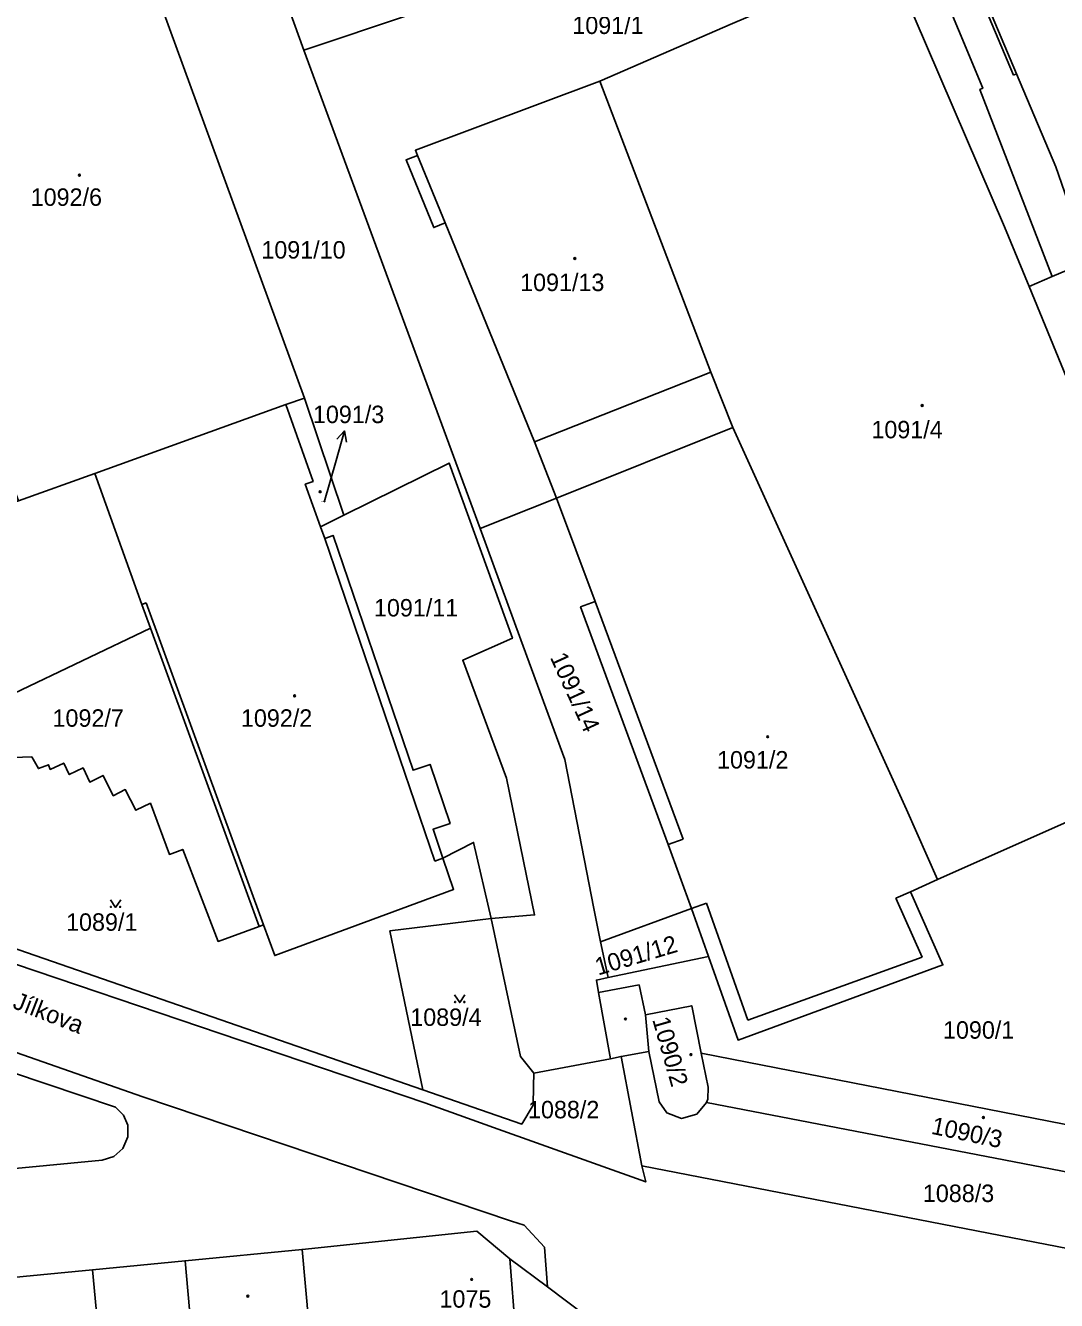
# Model space of a CAD drawing. Extents: x -596233 to -595156, y -1161235 to -1159375.
# Drawn here: x -596146 to -596045.4, y -1160887.6 to -1160763.3 of the extents above; entities that cross this region are included whole.
import ezdxf

# ---------------------------------------------------------------- set-up
doc = ezdxf.new("R2010")
doc.units = 0
for name, color, linetype in [('KN_CAR_KR', 7, 'Continuous'), ('KN_KULTURY', 7, 'Continuous'), ('KN_PARC_CIS_POM', 7, 'Continuous'), ('KN_PARC_CIS_POZ', 7, 'Continuous'), ('KN_PARC_CIS_STAV', 7, 'Continuous'), ('KN_PARC_PLOCHA', 7, 'Continuous'), ('KN_ULICE', 7, 'Continuous'), ('PARC_C_SIPKA', 7, 'Continuous'), ('parcely_l', 7, 'Continuous')]:
    doc.layers.add(name, color=color, linetype=linetype)

msp = doc.modelspace()

# ---------------------------------------------------------------- linework, layer by layer
at = {"layer": 'KN_CAR_KR'}
for points in [[(-596072.15, -1160714.71), (-596049.62, -1160768.1)], [(-596049.34, -1160767.98), (-596049.62, -1160768.1)], [(-596107.74, -1160775.93), (-596105.04, -1160782.51)], [(-596096.32, -1160803.86), (-596079.15, -1160797.08)], [(-596116.78, -1160813.27), (-596106.06, -1160844.74)], [(-596134.2, -1160819.54), (-596134.62, -1160819.7)], [(-596134.2, -1160819.54), (-596122.75, -1160850.94)], [(-596090.43, -1160819.42), (-596081.84, -1160842.59)], [(-596081.84, -1160842.59), (-596083.29, -1160843.12)], [(-596105.26, -1160844.44), (-596106.06, -1160844.74)], [(-596059.69, -1160847.71), (-596061.11, -1160848.34)], [(-596058.55, -1160854.09), (-596061.11, -1160848.34)], [(-596081.02, -1160849.36), (-596079.57, -1160848.83)], [(-596079.57, -1160848.83), (-596075.54, -1160860.23)], [(-596075.54, -1160860.23), (-596058.55, -1160854.09)], [(-596085.5, -1160859.72), (-596085.19, -1160863.29)]]:
    msp.add_lwpolyline(points, dxfattribs=at)
at = {"layer": 'KN_KULTURY'}
for points in [[(-596137.6818, -1160848.4916), (-596137.1818, -1160849.2416), (-596136.6818, -1160848.4916)], [(-596104.1218, -1160857.7616), (-596103.6218, -1160858.5116), (-596103.1218, -1160857.7616)]]:
    msp.add_lwpolyline(points, dxfattribs=at)
for centre, radius in [((-596140.71, -1160777.86), 0.09), ((-596140.71, -1160777.86), 0.0398), ((-596092.41, -1160785.98), 0.09), ((-596092.41, -1160785.98), 0.0398), ((-596058.53, -1160800.32), 0.09), ((-596058.53, -1160800.32), 0.0398), ((-596117.24, -1160808.72), 0.09), ((-596117.24, -1160808.72), 0.0398), ((-596119.72, -1160828.62), 0.09), ((-596119.72, -1160828.62), 0.0398), ((-596073.6, -1160832.6), 0.09), ((-596073.6, -1160832.6), 0.0398), ((-596137.632, -1160849.1914), 0.05), ((-596136.7326, -1160849.1914), 0.05), ((-596104.072, -1160858.4614), 0.05), ((-596103.1726, -1160858.4614), 0.05), ((-596087.47, -1160860.12), 0.09), ((-596087.47, -1160860.12), 0.0398), ((-596081.08, -1160863.59), 0.09), ((-596081.08, -1160863.59), 0.0398), ((-596052.57, -1160869.72), 0.09), ((-596052.57, -1160869.72), 0.0398), ((-596102.46, -1160885.5), 0.09), ((-596102.46, -1160885.5), 0.0398), ((-596124.29, -1160887.14), 0.09), ((-596124.29, -1160887.14), 0.0398)]:
    msp.add_circle(centre, radius, dxfattribs=at)
at = {"layer": 'KN_PARC_PLOCHA'}
for points in [[(-596000.33, -1160909.55), (-596007.39, -1160887.14), (-596011.7, -1160881.28), (-596019.9, -1160853.74), (-596021.03, -1160850.45), (-596021.41, -1160848.45), (-596026.6, -1160833.01), (-596028.99, -1160825.87), (-596038.75, -1160796.73), (-596042.32, -1160786.24), (-596045.52, -1160777.05), (-596049.34, -1160767.98), (-596071.87, -1160714.59), (-596073.58, -1160710.49), (-596068.84, -1160708.45), (-596077.52, -1160688.01)], [(-596136.48, -1160716.79), (-596118.84, -1160765.69), (-596101.64, -1160812.31), (-596097.66, -1160823.15), (-596093.37, -1160834.81), (-596090.56, -1160849.36), (-596089.9, -1160852.59), (-596089.16, -1160856.08), (-596090.3, -1160856.32), (-596090.08, -1160857.55), (-596088.92, -1160863.99), (-596096.41, -1160865.4), (-596097.7, -1160863.78), (-596100.56, -1160850.33), (-596096.33, -1160849.98), (-596099.08, -1160836.65), (-596103.33, -1160825.15), (-596098.49, -1160823.01), (-596104.65, -1160805.93), (-596114.93, -1160810.99), (-596118.75, -1160799.6), (-596137.5, -1160748.21)], [(-596059.58, -1160752.69), (-596052.63, -1160769.38), (-596052.9, -1160769.5), (-596045.86, -1160787.75), (-596048.11, -1160788.71), (-596050.5, -1160782.91), (-596061.82, -1160756.58)], [(-596077.03, -1160763.09), (-596089.98, -1160768.71), (-596107.94, -1160775.43), (-596107.74, -1160775.93), (-596108.85, -1160776.38), (-596106.16, -1160782.97), (-596105.04, -1160782.51), (-596096.32, -1160803.86), (-596094.2, -1160809.34), (-596101.64, -1160812.31), (-596118.84, -1160765.69), (-596108.43, -1160762.2)], [(-596152.74, -1160834.82), (-596145.36, -1160834.57), (-596144.7, -1160835.71), (-596143.73, -1160835.33), (-596143.55, -1160835.79), (-596142.23, -1160835.17), (-596141.7, -1160836.29), (-596140.34, -1160835.65), (-596139.69, -1160837.02), (-596138.4, -1160836.37), (-596137.4, -1160838.35), (-596136.23, -1160837.76), (-596135.21, -1160839.77), (-596133.78, -1160839.09), (-596131.93, -1160844.08), (-596130.63, -1160843.58), (-596127.18, -1160852.56), (-596123.17, -1160851.1), (-596122.75, -1160850.94), (-596121.66, -1160853.93), (-596104.23, -1160847.48), (-596105.26, -1160844.44), (-596102.27, -1160842.91), (-596100.56, -1160850.33), (-596110.43, -1160851.53), (-596107.22, -1160867.02), (-596171.31, -1160844.82)], [(-596027.09, -1160873.82), (-596080.08, -1160863.44), (-596081, -1160858.83), (-596085.5, -1160859.72), (-596086.13, -1160856.79), (-596090.08, -1160857.55), (-596090.3, -1160856.32), (-596089.16, -1160856.08), (-596079.37, -1160854.02), (-596076.49, -1160862.18), (-596056.52, -1160854.84), (-596059.69, -1160847.71), (-596057.04, -1160846.53), (-596033.57, -1160836.1)], [(-596168.84, -1160847.35), (-596107.03, -1160868.29), (-596100.34, -1160870.7), (-596085.49, -1160876), (-596085.86, -1160874.42), (-596010.41, -1160889.08)], [(-596200.45, -1160893.61), (-596199.88, -1160880.8), (-596201.49, -1160880.22), (-596202.73, -1160877.09), (-596202.04, -1160860.49), (-596201.91, -1160858.83), (-596201.86, -1160856.94), (-596199.63, -1160855.05), (-596180.91, -1160853.37), (-596176.85, -1160853.65), (-596170.3, -1160855.19), (-596134.51, -1160867.71), (-596098.58, -1160879.83), (-596097.34, -1160880.21), (-596095.37, -1160882.37), (-596095.08, -1160886.24), (-596098.74, -1160883.49), (-596101.95, -1160880.79), (-596118.99, -1160882.58), (-596130.41, -1160883.69), (-596139.42, -1160884.56), (-596153.99, -1160885.97), (-596163, -1160886.84), (-596171.46, -1160887.66)], [(-596083.82, -1160894.71), (-596095.08, -1160886.24), (-596095.37, -1160882.37), (-596097.34, -1160880.21), (-596098.58, -1160879.83), (-596134.51, -1160867.71), (-596170.3, -1160855.19)], [(-596097.64, -1160897.55), (-596098.74, -1160883.49), (-596095.08, -1160886.24), (-596083.82, -1160894.71)]]:
    msp.add_lwpolyline(points, dxfattribs=at)
for points in [[(-596118.84, -1160765.69), (-596136.48, -1160716.79), (-596124.3, -1160710.76), (-596108, -1160702.81), (-596087.28, -1160692.71), (-596087.37, -1160692.59), (-596086.66, -1160692.24), (-596082.71, -1160700.79), (-596087.62, -1160703.18), (-596086.79, -1160704.91), (-596089.87, -1160706.41), (-596086.76, -1160713.86), (-596082.9, -1160712.34), (-596067.77, -1160750.79), (-596096.45, -1160762.05), (-596111.56, -1160723.59), (-596107.01, -1160721.76), (-596109.61, -1160715.2), (-596122.95, -1160721.71), (-596112.01, -1160744.47), (-596104.98, -1160760.52), (-596108.43, -1160762.2)], [(-596042.32, -1160786.24), (-596045.86, -1160787.75), (-596052.9, -1160769.5), (-596052.63, -1160769.38), (-596059.58, -1160752.69), (-596058.71, -1160752.32), (-596073.95, -1160715.48), (-596072.15, -1160714.71), (-596071.87, -1160714.59), (-596049.34, -1160767.98), (-596045.52, -1160777.05)], [(-596118.75, -1160799.6), (-596120.58, -1160800.23), (-596139.2, -1160806.93), (-596146.64, -1160809.6), (-596163.39, -1160764.31), (-596175.3, -1160768.35), (-596177.14, -1160762.95), (-596137.5, -1160748.21)], [(-596177.14, -1160762.95), (-596175.3, -1160768.35), (-596158.5, -1160813.85), (-596146.64, -1160809.6), (-596139.2, -1160806.93), (-596134.62, -1160819.7), (-596133.78, -1160822.01), (-596153.81, -1160831.58), (-596157.33, -1160820.92), (-596182.87, -1160824.1), (-596185.5, -1160814.72), (-596176.78, -1160812.84), (-596185.99, -1160770.64), (-596197.16, -1160773.1), (-596199.82, -1160763.59), (-596180.21, -1160753.92)], [(-596048.11, -1160788.71), (-596043.93, -1160798.86), (-596031.4, -1160826.94), (-596028.36, -1160833.79), (-596033.57, -1160836.1), (-596057.04, -1160846.53), (-596060.08, -1160839.68), (-596077, -1160802.47), (-596079.15, -1160797.08), (-596089.98, -1160768.71), (-596077.03, -1160763.09), (-596061.82, -1160756.58), (-596050.5, -1160782.91)], [(-596077, -1160802.47), (-596094.2, -1160809.34), (-596096.32, -1160803.86), (-596105.04, -1160782.51), (-596106.16, -1160782.97), (-596108.85, -1160776.38), (-596107.74, -1160775.93), (-596107.94, -1160775.43), (-596089.98, -1160768.71), (-596079.15, -1160797.08)], [(-596028.99, -1160825.87), (-596031.4, -1160826.94), (-596043.93, -1160798.86), (-596048.11, -1160788.71), (-596045.86, -1160787.75), (-596042.32, -1160786.24), (-596038.75, -1160796.73)], [(-596117.19, -1160812.14), (-596116.78, -1160813.27), (-596115.98, -1160812.98), (-596108.18, -1160835.87), (-596106.52, -1160835.3), (-596104.56, -1160841.06), (-596106.22, -1160841.62), (-596105.26, -1160844.44), (-596104.23, -1160847.48), (-596121.66, -1160853.93), (-596122.75, -1160850.94), (-596123.17, -1160851.1), (-596133.78, -1160822.01), (-596134.62, -1160819.7), (-596139.2, -1160806.93), (-596120.58, -1160800.23), (-596117.93, -1160807.72), (-596118.68, -1160807.99)], [(-596114.93, -1160810.99), (-596117.19, -1160812.14), (-596118.68, -1160807.99), (-596117.93, -1160807.72), (-596120.58, -1160800.23), (-596118.75, -1160799.6)], [(-596057.04, -1160846.53), (-596059.69, -1160847.71), (-596056.52, -1160854.84), (-596076.49, -1160862.18), (-596079.37, -1160854.02), (-596081.02, -1160849.36), (-596083.29, -1160843.12), (-596091.84, -1160819.95), (-596090.43, -1160819.42), (-596094.2, -1160809.34), (-596077, -1160802.47), (-596060.08, -1160839.68)], [(-596100.56, -1160850.33), (-596102.27, -1160842.91), (-596105.26, -1160844.44), (-596106.22, -1160841.62), (-596104.56, -1160841.06), (-596106.52, -1160835.3), (-596108.18, -1160835.87), (-596115.98, -1160812.98), (-596116.78, -1160813.27), (-596117.19, -1160812.14), (-596114.93, -1160810.99), (-596104.65, -1160805.93), (-596098.49, -1160823.01), (-596103.33, -1160825.15), (-596099.08, -1160836.65), (-596096.33, -1160849.98)], [(-596081.02, -1160849.36), (-596089.9, -1160852.59), (-596090.56, -1160849.36), (-596093.37, -1160834.81), (-596097.66, -1160823.15), (-596101.64, -1160812.31), (-596094.2, -1160809.34), (-596090.43, -1160819.42), (-596091.84, -1160819.95), (-596083.29, -1160843.12)], [(-596123.17, -1160851.1), (-596127.18, -1160852.56), (-596130.63, -1160843.58), (-596131.93, -1160844.08), (-596133.78, -1160839.09), (-596135.21, -1160839.77), (-596136.23, -1160837.76), (-596137.4, -1160838.35), (-596138.4, -1160836.37), (-596139.69, -1160837.02), (-596140.34, -1160835.65), (-596141.7, -1160836.29), (-596142.23, -1160835.17), (-596143.55, -1160835.79), (-596143.73, -1160835.33), (-596144.7, -1160835.71), (-596145.36, -1160834.57), (-596152.74, -1160834.82), (-596153.81, -1160831.58), (-596133.78, -1160822.01)], [(-596107.22, -1160867.02), (-596097.58, -1160870.36), (-596096.48, -1160868.53), (-596096.44, -1160866.67), (-596096.41, -1160865.4), (-596088.92, -1160863.99), (-596087.89, -1160863.76), (-596085.86, -1160874.42), (-596085.49, -1160876), (-596100.34, -1160870.7), (-596107.03, -1160868.29), (-596168.84, -1160847.35), (-596175.49, -1160845.77), (-596180.4, -1160845.39), (-596181.92, -1160845.45), (-596178.19, -1160843.57), (-596177.81, -1160843.55), (-596171.31, -1160844.82)], [(-596079.37, -1160854.02), (-596089.16, -1160856.08), (-596089.9, -1160852.59), (-596081.02, -1160849.36)], [(-596096.41, -1160865.4), (-596096.44, -1160866.67), (-596096.48, -1160868.53), (-596097.58, -1160870.36), (-596107.22, -1160867.02), (-596110.43, -1160851.53), (-596100.56, -1160850.33), (-596097.7, -1160863.78)], [(-596138.5, -1160873.88), (-596191.79, -1160878.99), (-596191.14, -1160856.53), (-596179.67, -1160855.28), (-596176.6, -1160855.55), (-596174.51, -1160856.16), (-596137.2, -1160868.71), (-596136.41, -1160869.5), (-596136, -1160870.46), (-596135.98, -1160871.59), (-596136.48, -1160872.74), (-596137.35, -1160873.52)], [(-596138.5, -1160873.88), (-596137.35, -1160873.52), (-596136.48, -1160872.74), (-596135.98, -1160871.59), (-596136, -1160870.46), (-596136.41, -1160869.5), (-596137.2, -1160868.71), (-596174.51, -1160856.16), (-596176.6, -1160855.55), (-596179.67, -1160855.28), (-596191.14, -1160856.53), (-596191.79, -1160878.99)], [(-596080.08, -1160863.44), (-596079.41, -1160866.78), (-596079.43, -1160867.93), (-596079.56, -1160868.27), (-596080.51, -1160869.4), (-596081.99, -1160869.81), (-596083.44, -1160869.28), (-596084.19, -1160868.2), (-596085.19, -1160863.29), (-596087.89, -1160863.76), (-596088.92, -1160863.99), (-596090.08, -1160857.55), (-596086.13, -1160856.79), (-596085.5, -1160859.72), (-596081, -1160858.83)], [(-596079.56, -1160868.27), (-596026.81, -1160878.44), (-596019.85, -1160879.75), (-596011.7, -1160881.28), (-596007.39, -1160887.14), (-596000.33, -1160909.55), (-596012, -1160905.25), (-596014.53, -1160904.19), (-596006.25, -1160900.53), (-596009.92, -1160899.18), (-596010.61, -1160897.55), (-596010.41, -1160889.08), (-596085.86, -1160874.42), (-596087.89, -1160863.76), (-596085.19, -1160863.29), (-596084.19, -1160868.2), (-596083.44, -1160869.28), (-596081.99, -1160869.81), (-596080.51, -1160869.4)], [(-596026.81, -1160878.44), (-596079.56, -1160868.27), (-596079.43, -1160867.93), (-596079.41, -1160866.78), (-596080.08, -1160863.44), (-596027.09, -1160873.82), (-596026.58, -1160878.07)], [(-596098.74, -1160883.49), (-596097.64, -1160897.55), (-596107.71, -1160898.29), (-596107.94, -1160898.31), (-596111.91, -1160898.65), (-596117.49, -1160899.12), (-596117.88, -1160894.84), (-596118.01, -1160893.42), (-596118.99, -1160882.58), (-596101.95, -1160880.79)], [(-596117.88, -1160894.84), (-596123.34, -1160895.34), (-596123.08, -1160898.14), (-596122.97, -1160899.12), (-596124.24, -1160900.95), (-596129.06, -1160901.42), (-596129.09, -1160898.69), (-596129.09, -1160898.46), (-596129.17, -1160897.57), (-596130.41, -1160883.69), (-596118.99, -1160882.58), (-596118.01, -1160893.42)], [(-596137.68, -1160903.28), (-596137.46, -1160905.73), (-596137.39, -1160906.48), (-596144.44, -1160906.38), (-596144.93, -1160901.29), (-596145.14, -1160899.13), (-596145.03, -1160899.12), (-596145.23, -1160897.26), (-596149.52, -1160897.65), (-596149.91, -1160901.78), (-596153.2, -1160902.09), (-596152.84, -1160897.91), (-596153.99, -1160885.97), (-596139.42, -1160884.56), (-596138.13, -1160898.4)], [(-596129.06, -1160901.42), (-596129.05, -1160902.48), (-596137.68, -1160903.28), (-596138.13, -1160898.4), (-596139.42, -1160884.56), (-596130.41, -1160883.69), (-596129.17, -1160897.57), (-596129.09, -1160898.46), (-596129.09, -1160898.69)]]:
    msp.add_lwpolyline(points, close=True, dxfattribs=at)
at = {"layer": 'PARC_C_SIPKA'}
for points in [[(-596116.83, -1160809.73), (-596115.68, -1160805.67), (-596114.8619, -1160802.7837)], [(-596115.6156, -1160803.6095), (-596114.8619, -1160802.7837), (-596114.6535, -1160803.8822)]]:
    msp.add_lwpolyline(points, dxfattribs=at)
at = {"layer": 'parcely_l'}
for points in [[(-596086.66, -1160692.24), (-596082.71, -1160700.79), (-596087.62, -1160703.18), (-596086.79, -1160704.91), (-596089.87, -1160706.41), (-596086.76, -1160713.86), (-596082.9, -1160712.34), (-596067.77, -1160750.79), (-596096.45, -1160762.05), (-596111.56, -1160723.59), (-596107.01, -1160721.76), (-596109.61, -1160715.2), (-596122.95, -1160721.71), (-596112.01, -1160744.47), (-596104.98, -1160760.52), (-596108.43, -1160762.2), (-596118.84, -1160765.69)], [(-596045.86, -1160787.75), (-596052.9, -1160769.5), (-596052.63, -1160769.38), (-596059.58, -1160752.69), (-596058.71, -1160752.32), (-596073.95, -1160715.48), (-596072.15, -1160714.71), (-596071.87, -1160714.59)], [(-596071.87, -1160714.59), (-596049.34, -1160767.98), (-596045.52, -1160777.05), (-596042.32, -1160786.24)], [(-596136.48, -1160716.79), (-596118.84, -1160765.69)], [(-596118.75, -1160799.6), (-596137.5, -1160748.21)], [(-596089.98, -1160768.71), (-596077.03, -1160763.09), (-596061.82, -1160756.58), (-596050.5, -1160782.91), (-596048.11, -1160788.71)], [(-596118.84, -1160765.69), (-596101.64, -1160812.31)], [(-596094.2, -1160809.34), (-596096.32, -1160803.86), (-596105.04, -1160782.51), (-596106.16, -1160782.97), (-596108.85, -1160776.38), (-596107.74, -1160775.93), (-596107.94, -1160775.43), (-596089.98, -1160768.71)], [(-596077, -1160802.47), (-596079.15, -1160797.08), (-596089.98, -1160768.71)], [(-596045.86, -1160787.75), (-596042.32, -1160786.24)], [(-596048.11, -1160788.71), (-596045.86, -1160787.75)], [(-596031.4, -1160826.94), (-596043.93, -1160798.86), (-596048.11, -1160788.71)], [(-596120.58, -1160800.23), (-596139.2, -1160806.93)], [(-596118.75, -1160799.6), (-596120.58, -1160800.23)], [(-596120.58, -1160800.23), (-596117.93, -1160807.72), (-596118.68, -1160807.99), (-596117.19, -1160812.14)], [(-596114.93, -1160810.99), (-596118.75, -1160799.6)], [(-596094.2, -1160809.34), (-596077, -1160802.47)], [(-596057.04, -1160846.53), (-596060.08, -1160839.68), (-596077, -1160802.47)], [(-596100.56, -1160850.33), (-596096.33, -1160849.98), (-596099.08, -1160836.65), (-596103.33, -1160825.15), (-596098.49, -1160823.01), (-596104.65, -1160805.93), (-596114.93, -1160810.99)], [(-596139.2, -1160806.93), (-596146.64, -1160809.6)], [(-596133.78, -1160822.01), (-596134.62, -1160819.7), (-596139.2, -1160806.93)], [(-596101.64, -1160812.31), (-596094.2, -1160809.34)], [(-596081.02, -1160849.36), (-596083.29, -1160843.12), (-596091.84, -1160819.95), (-596090.43, -1160819.42), (-596094.2, -1160809.34)], [(-596114.93, -1160810.99), (-596117.19, -1160812.14)], [(-596117.19, -1160812.14), (-596116.78, -1160813.27), (-596115.98, -1160812.98), (-596108.18, -1160835.87), (-596106.52, -1160835.3), (-596104.56, -1160841.06), (-596106.22, -1160841.62), (-596105.26, -1160844.44)], [(-596101.64, -1160812.31), (-596097.66, -1160823.15), (-596093.37, -1160834.81), (-596090.56, -1160849.36), (-596089.9, -1160852.59)], [(-596153.81, -1160831.58), (-596133.78, -1160822.01)], [(-596133.78, -1160822.01), (-596123.17, -1160851.1)], [(-596123.17, -1160851.1), (-596127.18, -1160852.56), (-596130.63, -1160843.58), (-596131.93, -1160844.08), (-596133.78, -1160839.09), (-596135.21, -1160839.77), (-596136.23, -1160837.76), (-596137.4, -1160838.35), (-596138.4, -1160836.37), (-596139.69, -1160837.02), (-596140.34, -1160835.65), (-596141.7, -1160836.29), (-596142.23, -1160835.17), (-596143.55, -1160835.79), (-596143.73, -1160835.33), (-596144.7, -1160835.71), (-596145.36, -1160834.57), (-596152.74, -1160834.82)], [(-596057.04, -1160846.53), (-596033.57, -1160836.1)], [(-596085.86, -1160874.42), (-596085.49, -1160876), (-596100.34, -1160870.7), (-596107.03, -1160868.29), (-596168.84, -1160847.35), (-596175.49, -1160845.77), (-596180.4, -1160845.39), (-596181.92, -1160845.45), (-596178.19, -1160843.57)], [(-596178.19, -1160843.57), (-596177.81, -1160843.55), (-596171.31, -1160844.82), (-596107.22, -1160867.02)], [(-596105.26, -1160844.44), (-596102.27, -1160842.91), (-596100.56, -1160850.33)], [(-596123.17, -1160851.1), (-596122.75, -1160850.94), (-596121.66, -1160853.93), (-596104.23, -1160847.48), (-596105.26, -1160844.44)], [(-596079.37, -1160854.02), (-596076.49, -1160862.18), (-596056.52, -1160854.84), (-596059.69, -1160847.71), (-596057.04, -1160846.53)], [(-596089.9, -1160852.59), (-596081.02, -1160849.36)], [(-596079.37, -1160854.02), (-596081.02, -1160849.36)], [(-596100.56, -1160850.33), (-596110.43, -1160851.53), (-596107.22, -1160867.02)], [(-596096.41, -1160865.4), (-596097.7, -1160863.78), (-596100.56, -1160850.33)], [(-596201.86, -1160856.94), (-596199.63, -1160855.05), (-596180.91, -1160853.37), (-596176.85, -1160853.65), (-596170.3, -1160855.19), (-596134.51, -1160867.71), (-596098.58, -1160879.83), (-596097.34, -1160880.21), (-596095.37, -1160882.37), (-596095.08, -1160886.24)], [(-596089.9, -1160852.59), (-596089.16, -1160856.08)], [(-596089.16, -1160856.08), (-596079.37, -1160854.02)], [(-596138.5, -1160873.88), (-596137.35, -1160873.52), (-596136.48, -1160872.74), (-596135.98, -1160871.59), (-596136, -1160870.46), (-596136.41, -1160869.5), (-596137.2, -1160868.71), (-596174.51, -1160856.16), (-596176.6, -1160855.55), (-596179.67, -1160855.28), (-596191.14, -1160856.53), (-596191.79, -1160878.99), (-596138.5, -1160873.88)], [(-596090.08, -1160857.55), (-596090.3, -1160856.32), (-596089.16, -1160856.08)], [(-596080.08, -1160863.44), (-596081, -1160858.83), (-596085.5, -1160859.72), (-596086.13, -1160856.79), (-596090.08, -1160857.55)], [(-596090.08, -1160857.55), (-596088.92, -1160863.99)], [(-596079.56, -1160868.27), (-596080.51, -1160869.4), (-596081.99, -1160869.81), (-596083.44, -1160869.28), (-596084.19, -1160868.2), (-596085.19, -1160863.29), (-596087.89, -1160863.76)], [(-596026.81, -1160878.44), (-596026.58, -1160878.07), (-596027.09, -1160873.82), (-596080.08, -1160863.44)], [(-596080.08, -1160863.44), (-596079.41, -1160866.78), (-596079.43, -1160867.93), (-596079.56, -1160868.27)], [(-596088.92, -1160863.99), (-596096.41, -1160865.4)], [(-596087.89, -1160863.76), (-596088.92, -1160863.99)], [(-596087.89, -1160863.76), (-596085.86, -1160874.42)], [(-596107.22, -1160867.02), (-596097.58, -1160870.36), (-596096.48, -1160868.53), (-596096.44, -1160866.67), (-596096.41, -1160865.4)], [(-596026.81, -1160878.44), (-596079.56, -1160868.27)], [(-596014.53, -1160904.19), (-596006.25, -1160900.53), (-596009.92, -1160899.18), (-596010.61, -1160897.55), (-596010.41, -1160889.08), (-596085.86, -1160874.42)], [(-596118.99, -1160882.58), (-596101.95, -1160880.79), (-596098.74, -1160883.49)], [(-596118.99, -1160882.58), (-596130.41, -1160883.69)], [(-596117.88, -1160894.84), (-596118.01, -1160893.42), (-596118.99, -1160882.58)], [(-596098.74, -1160883.49), (-596097.64, -1160897.55)], [(-596095.08, -1160886.24), (-596098.74, -1160883.49)], [(-596153.99, -1160885.97), (-596139.42, -1160884.56)], [(-596130.41, -1160883.69), (-596139.42, -1160884.56)], [(-596139.42, -1160884.56), (-596138.13, -1160898.4), (-596137.68, -1160903.28)], [(-596129.06, -1160901.42), (-596129.09, -1160898.69), (-596129.09, -1160898.46), (-596129.17, -1160897.57), (-596130.41, -1160883.69)], [(-596095.08, -1160886.24), (-596083.82, -1160894.71)]]:
    msp.add_lwpolyline(points, dxfattribs=at)

# ---------------------------------------------------------------- texts
at = {"layer": 'KN_PARC_CIS_POM'}
msp.add_text('1091/3', height=0.1, dxfattribs=at).set_placement((-596117.1133, -1160809.73))
at = {"layer": 'KN_PARC_CIS_POZ'}
for s, p in [('1091/1', (-596092.6466, -1160764.1)), ('1091/10', (-596122.9666, -1160785.99)), ('1091/11', (-596111.9866, -1160820.88)), ('1092/7', (-596143.3266, -1160831.63)), ('1089/1', (-596142.0066, -1160851.52)), ('1089/4', (-596108.4466, -1160860.79)), ('1090/1', (-596056.5066, -1160862.04)), ('1088/2', (-596096.9666, -1160869.8)), ('1088/3', (-596058.4666, -1160877.96))]:
    msp.add_text(s, height=1.7, dxfattribs=at).set_placement(p)
for s, rotation, p in [('1091/14', 294.563018, (-596094.8556, -1160824.8562)), ('1091/12', 16.599631, (-596090.1338, -1160855.888))]:
    msp.add_text(s, height=1.7, rotation=rotation, dxfattribs=at).set_placement(p)
at = {"layer": 'KN_PARC_CIS_STAV'}
for s, p in [('1092/6', (-596145.4566, -1160780.85)), ('1091/13', (-596097.7366, -1160789.16)), ('1091/3', (-596117.9366, -1160802.03)), ('1091/4', (-596063.4866, -1160803.51)), ('1092/2', (-596124.9566, -1160831.63)), ('1091/2', (-596078.5366, -1160835.7)), ('1075', (-596105.5966, -1160888.26))]:
    msp.add_text(s, height=1.7, dxfattribs=at).set_placement(p)
for s, rotation, p in [('1090/2', 285.939576, (-596084.8628, -1160860.1686)), ('1090/3', 348.238703, (-596057.7355, -1160871.2982))]:
    msp.add_text(s, height=1.7, rotation=rotation, dxfattribs=at).set_placement(p)
at = {"layer": 'KN_ULICE'}
msp.add_text('Jílkova', height=1.7, rotation=338.717883, dxfattribs=at).set_placement((-596147.3102, -1160859.0232))

doc.saveas('drawing.dxf')
